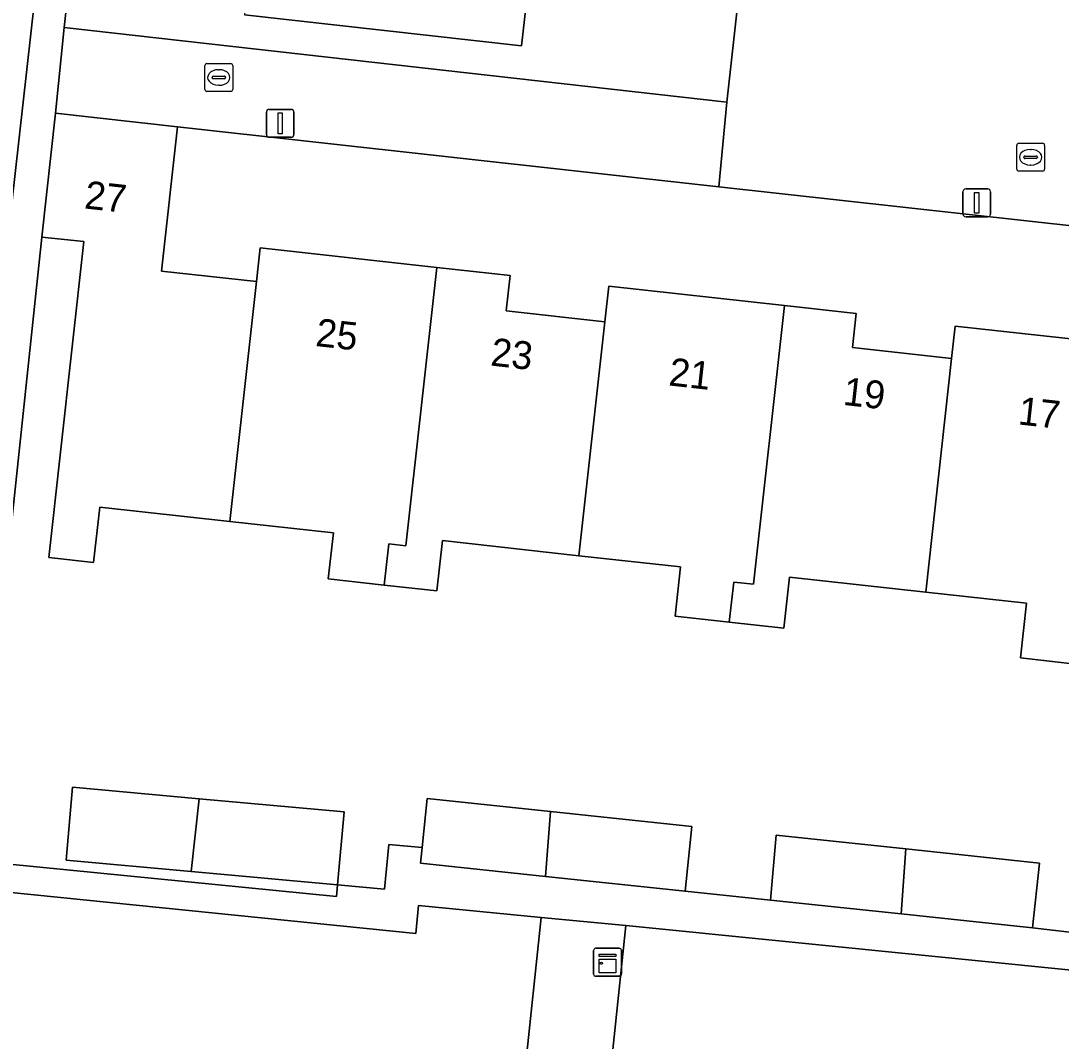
# Model space of a CAD drawing. Extents: x 162082 to 163401, y 388089 to 388636.
# Drawn here: x 162798.94 to 162836.27, y 388127.59 to 388164.2 of the extents above; entities that cross this region are included whole.
import ezdxf

# ---------------------------------------------------------------- set-up
doc = ezdxf.new("R2010")
doc.units = 0
for name, color, linetype in [('IMGEO_Brandkraan', 7, 'Continuous'), ('IMGEO_Erf', 7, 'Continuous'), ('IMGEO_Kast', 7, 'Continuous'), ('IMGEO_Lichtmast', 7, 'Continuous'), ('IMGEO_Muur', 7, 'Continuous'), ('IMGEO_Pand', 7, 'Continuous'), ('IMGEO_Pand_nummerreeks', 7, 'Continuous'), ('IMGEO_Rijbaan_lokaal_open', 7, 'Continuous'), ('IMGEO_Rioolput', 7, 'Continuous'), ('IMGEO_Voetpad_open', 7, 'Continuous')]:
    doc.layers.add(name, color=color, linetype=linetype)

msp = doc.modelspace()

# ---------------------------------------------------------------- linework, layer by layer
at = {"layer": 'IMGEO_Brandkraan'}
for p, q in [((162805.621, 388162.671), (162806.473, 388162.671)), ((162805.546, 388161.745), (162805.546, 388162.597)), ((162806.034, 388162.451), (162806.059, 388162.451)), ((162806.547, 388162.597), (162806.547, 388161.745)), ((162805.805, 388162.165), (162805.805, 388162.177)), ((162806.243, 388162.128), (162805.845, 388162.128)), ((162805.848, 388162.214), (162806.246, 388162.214)), ((162806.057, 388161.891), (162806.032, 388161.891)), ((162806.289, 388162.177), (162806.289, 388162.165)), ((162806.473, 388161.671), (162805.621, 388161.671))]:
    msp.add_line(p, q, dxfattribs=at)
for points in [[(162805.621, 388162.671), (162806.473, 388162.671)], [(162805.546, 388161.745), (162805.546, 388162.597)], [(162806.547, 388162.597), (162806.547, 388161.745)], [(162806.473, 388161.671), (162805.621, 388161.671)]]:
    msp.add_lwpolyline(points, dxfattribs=at)
for centre, radius, start, end in [((162805.623, 388162.595), 0.0765, 91.552, 178.448), ((162805.623, 388162.595), 0.0765, 91.552, 178.448), ((162806.471, 388162.595), 0.0765, 1.552, 88.448), ((162806.471, 388162.595), 0.0765, 1.552, 88.448), ((162805.845, 388162.174), 0.0403, 85.8775, 175.7526), ((162805.842, 388162.164), 0.0366, 178.938, 274.7102), ((162806.246, 388162.171), 0.043, 264.8664, 352.4533), ((162806.25, 388162.176), 0.0386, 1.7309, 96.639), ((162805.623, 388161.747), 0.0765, 181.552, 268.448), ((162805.623, 388161.747), 0.0765, 181.552, 268.448), ((162806.471, 388161.747), 0.0765, 271.552, 358.448), ((162806.471, 388161.747), 0.0765, 271.552, 358.448)]:
    msp.add_arc(centre, radius, start, end, dxfattribs=at)
for centre, major_axis, ratio, start_param, end_param in [((162806.033, 388162.171), (-0.387, 0.002), 0.722429, 4.712389, 7.853982), ((162806.058, 388162.171), (-0.39, 0.002), 0.717154, 1.570796, 4.712389)]:
    msp.add_ellipse(centre, major_axis=major_axis, ratio=ratio, start_param=start_param, end_param=end_param, dxfattribs=at)
at = {"layer": 'IMGEO_Erf'}
for points in [[(162795.979, 388134.212), (162803.844, 388204.258)], [(162804.95, 388204.136), (162800.498, 388163.968), (162808.249, 388163.092), (162824.27, 388161.282), (162825.928, 388176.279)], [(162817.345, 388167.21), (162816.908, 388163.305), (162806.971, 388164.418)], [(162836.884, 388141.113), (162834.808, 388141.342), (162835.025, 388143.308), (162831.408, 388143.708), (162826.524, 388144.247), (162826.321, 388142.407), (162824.357, 388142.624), (162822.419, 388142.838), (162822.614, 388144.609), (162818.966, 388145.012), (162814.072, 388145.552), (162813.873, 388143.749), (162811.98, 388143.958), (162809.974, 388144.179), (162810.156, 388145.829), (162806.447, 388146.239), (162801.775, 388146.755), (162801.556, 388144.773), (162799.953, 388144.95), (162801.204, 388156.281), (162799.702, 388156.447), (162797.324, 388134.069), (162810.27, 388132.785), (162810.308, 388133.203), (162811.995, 388133.05), (162812.141, 388134.654), (162813.336, 388134.54), (162813.522, 388136.303), (162817.949, 388135.835), (162823.02, 388135.3), (162822.774, 388132.978), (162825.835, 388132.655), (162826.044, 388134.981), (162830.698, 388134.49), (162835.484, 388133.985), (162835.239, 388131.662), (162842.925, 388130.761)], [(162854.896, 388128.313), (162820.645, 388131.737), (162819.814, 388123.748), (162825.983, 388123.05), (162832, 388122.369), (162832.125, 388123.472), (162834.954, 388123.15), (162834.829, 388122.049), (162838.019, 388121.688)]]:
    msp.add_lwpolyline(points, dxfattribs=at)
for points in [[(162851.871, 388155.185), (162845.948, 388155.819), (162823.979, 388158.253), (162804.563, 388160.404), (162803.991, 388155.225), (162807.402, 388154.848), (162807.536, 388156.057), (162813.862, 388155.358), (162816.5, 388155.067), (162816.36, 388153.795), (162819.896, 388153.404), (162820.037, 388154.684), (162826.336, 388153.989), (162828.913, 388153.704), (162828.779, 388152.483), (162832.337, 388152.09), (162832.466, 388153.25), (162838.801, 388152.55), (162841.344, 388152.269), (162841.201, 388150.977), (162844.809, 388150.578), (162844.952, 388151.873), (162851.481, 388151.152), (162851.565, 388152.023)], [(162817.616, 388132.026), (162813.209, 388132.465), (162813.117, 388131.452), (162774.618, 388135.355), (162754.126, 388137.65), (162753.09, 388128.162), (162759.25, 388127.458), (162765.261, 388126.772), (162771.273, 388126.085), (162777.284, 388125.399), (162783.297, 388124.712), (162789.309, 388124.025), (162795.321, 388123.339), (162801.333, 388122.652), (162807.344, 388121.965), (162813.503, 388121.262), (162816.444, 388120.926)], [(162810.308, 388133.203), (162805.054, 388133.679), (162800.565, 388134.086), (162800.802, 388136.703), (162805.344, 388136.292), (162810.545, 388135.82)]]:
    msp.add_lwpolyline(points, close=True, dxfattribs=at)
at = {"layer": 'IMGEO_Kast'}
for p, q in [((162819.566, 388130.924), (162820.407, 388130.924)), ((162820.407, 388130.924), (162819.566, 388130.924)), ((162819.491, 388129.999), (162819.491, 388130.84)), ((162819.491, 388130.84), (162819.491, 388129.999)), ((162820.491, 388130.849), (162820.491, 388130.008)), ((162820.491, 388130.008), (162820.491, 388130.849)), ((162820.416, 388129.924), (162819.575, 388129.924)), ((162819.575, 388129.924), (162820.416, 388129.924))]:
    msp.add_line(p, q, dxfattribs=at)
for points in [[(162819.686, 388130.714), (162820.286, 388130.714), (162820.286, 388130.629), (162819.686, 388130.629), (162819.686, 388130.714)], [(162819.686, 388130.539), (162820.286, 388130.539), (162820.286, 388130.05), (162819.686, 388130.05), (162819.686, 388130.539)]]:
    msp.add_lwpolyline(points, dxfattribs=at)
msp.add_circle((162819.77, 388130.388), 0.0377, dxfattribs=at)
for centre, start, end in [((162819.569, 388130.846), 92.4484, 184.2845), ((162819.569, 388130.846), 92.4484, 184.2845), ((162820.413, 388130.846), 2.4484, 94.2845), ((162820.413, 388130.846), 2.4484, 94.2845), ((162819.569, 388130.002), 182.4484, 274.2845), ((162819.569, 388130.002), 182.4484, 274.2845), ((162820.413, 388130.002), 272.4484, 4.2845), ((162820.413, 388130.002), 272.4484, 4.2845)]:
    msp.add_arc(centre, 0.0779, start, end, dxfattribs=at)
at = {"layer": 'IMGEO_Lichtmast'}
for p, q in [((162807.753, 388160.124), (162807.753, 388160.924)), ((162807.753, 388160.924), (162807.753, 388160.124)), ((162807.853, 388161.024), (162808.643, 388161.024)), ((162808.643, 388161.024), (162807.853, 388161.024)), ((162808.743, 388160.924), (162808.743, 388160.124)), ((162808.743, 388160.124), (162808.743, 388160.924)), ((162808.643, 388160.024), (162807.853, 388160.024)), ((162807.853, 388160.024), (162808.643, 388160.024)), ((162832.84, 388158.172), (162833.63, 388158.172)), ((162833.63, 388158.172), (162832.84, 388158.172)), ((162832.74, 388157.272), (162832.74, 388158.072)), ((162832.74, 388158.072), (162832.74, 388157.272)), ((162833.73, 388158.072), (162833.73, 388157.272)), ((162833.73, 388157.272), (162833.73, 388158.072)), ((162833.63, 388157.172), (162832.84, 388157.172)), ((162832.84, 388157.172), (162833.63, 388157.172))]:
    msp.add_line(p, q, dxfattribs=at)
for points in [[(162808.173, 388160.899), (162808.323, 388160.899), (162808.323, 388160.149), (162808.173, 388160.149), (162808.173, 388160.899)], [(162833.16, 388158.047), (162833.31, 388158.047), (162833.31, 388157.297), (162833.16, 388157.297), (162833.16, 388158.047)]]:
    msp.add_lwpolyline(points, dxfattribs=at)
for centre, start, end in [((162807.853, 388160.924), 90, 180), ((162807.853, 388160.924), 90, 180), ((162808.643, 388160.924), 0, 90), ((162808.643, 388160.924), 360, 90), ((162807.853, 388160.124), 180, 270), ((162807.853, 388160.124), 180, 270), ((162808.643, 388160.124), 270, 0), ((162808.643, 388160.124), 270, 0), ((162832.84, 388158.072), 90, 180), ((162832.84, 388158.072), 90, 180), ((162833.63, 388158.072), 0, 90), ((162833.63, 388158.072), 360, 90), ((162832.84, 388157.272), 180, 270), ((162832.84, 388157.272), 180, 270), ((162833.63, 388157.272), 270, 0), ((162833.63, 388157.272), 270, 0)]:
    msp.add_arc(centre, 0.1, start, end, dxfattribs=at)
at = {"layer": 'IMGEO_Muur'}
msp.add_lwpolyline([(162800.498, 388163.968), (162808.249, 388163.092)], dxfattribs=at)
at = {"layer": 'IMGEO_Pand'}
for points in [[(162809.728, 388174.626), (162809.314, 388170.93), (162807.72, 388171.109), (162807.527, 388169.387), (162806.971, 388164.418), (162816.908, 388163.305), (162817.345, 388167.21), (162818.835, 388167.043), (162819.561, 388173.523), (162818.4, 388173.653)], [(162807.402, 388154.848), (162803.991, 388155.225), (162804.563, 388160.404), (162800.192, 388160.886), (162799.702, 388156.447), (162801.204, 388156.281), (162799.953, 388144.95), (162801.556, 388144.773), (162801.775, 388146.755), (162806.447, 388146.239)], [(162807.402, 388154.848), (162806.447, 388146.239), (162810.156, 388145.829), (162809.974, 388144.179), (162811.98, 388143.958), (162812.144, 388145.437), (162812.758, 388145.369), (162813.862, 388155.358), (162807.536, 388156.057)], [(162819.896, 388153.404), (162816.36, 388153.795), (162816.5, 388155.067), (162813.862, 388155.358), (162812.758, 388145.369), (162812.144, 388145.437), (162811.98, 388143.958), (162813.873, 388143.749), (162814.072, 388145.552), (162818.966, 388145.012)], [(162819.896, 388153.404), (162818.966, 388145.012), (162822.614, 388144.609), (162822.419, 388142.838), (162824.357, 388142.624), (162824.517, 388144.067), (162825.23, 388143.988), (162826.336, 388153.989), (162820.037, 388154.684)], [(162824.357, 388142.624), (162826.321, 388142.407), (162826.524, 388144.247), (162831.408, 388143.708), (162832.337, 388152.09), (162828.779, 388152.483), (162828.913, 388153.704), (162826.336, 388153.989), (162825.23, 388143.988), (162824.517, 388144.067)], [(162838.801, 388152.55), (162832.466, 388153.25), (162832.337, 388152.09), (162831.408, 388143.708), (162835.025, 388143.308), (162834.808, 388141.342), (162836.884, 388141.113), (162837.059, 388142.688), (162837.703, 388142.616)], [(162805.344, 388136.292), (162800.802, 388136.703), (162800.565, 388134.086), (162805.054, 388133.679)], [(162805.344, 388136.292), (162805.054, 388133.679), (162810.308, 388133.203), (162810.545, 388135.82)], [(162817.949, 388135.835), (162813.522, 388136.303), (162813.336, 388134.54), (162813.277, 388133.981), (162817.772, 388133.506)], [(162817.949, 388135.835), (162817.772, 388133.506), (162822.774, 388132.978), (162823.02, 388135.3)], [(162830.698, 388134.49), (162826.044, 388134.981), (162825.835, 388132.655), (162830.521, 388132.16)], [(162830.698, 388134.49), (162830.521, 388132.16), (162835.239, 388131.662), (162835.484, 388133.985)]]:
    msp.add_lwpolyline(points, close=True, dxfattribs=at)
at = {"layer": 'IMGEO_Rijbaan_lokaal_open'}
msp.add_lwpolyline([(162847.12, 388166.739), (162848.03, 388175.302), (162848.456, 388179.167), (162849.399, 388187.886), (162849.808, 388191.587), (162850.603, 388199.107), (162828.788, 388201.496), (162828.347, 388197.774), (162827.717, 388192.459), (162827.301, 388188.741), (162826.346, 388180.019), (162825.928, 388176.279), (162824.27, 388161.282), (162823.979, 388158.253), (162845.948, 388155.819), (162846.154, 388157.848), (162846.709, 388163.018)], close=True, dxfattribs=at)
at = {"layer": 'IMGEO_Rioolput'}
for p, q in [((162834.671, 388158.884), (162834.671, 388159.736)), ((162834.746, 388159.81), (162835.598, 388159.81)), ((162835.672, 388159.736), (162835.672, 388158.884)), ((162834.93, 388159.304), (162834.93, 388159.316)), ((162834.973, 388159.353), (162835.371, 388159.353)), ((162835.159, 388159.59), (162835.184, 388159.59)), ((162835.414, 388159.316), (162835.414, 388159.304)), ((162835.368, 388159.267), (162834.97, 388159.267)), ((162835.182, 388159.03), (162835.157, 388159.03)), ((162835.598, 388158.81), (162834.746, 388158.81))]:
    msp.add_line(p, q, dxfattribs=at)
for points in [[(162834.671, 388158.884), (162834.671, 388159.736)], [(162834.746, 388159.81), (162835.598, 388159.81)], [(162835.672, 388159.736), (162835.672, 388158.884)], [(162835.598, 388158.81), (162834.746, 388158.81)]]:
    msp.add_lwpolyline(points, dxfattribs=at)
for centre, radius, start, end in [((162834.748, 388159.734), 0.0765, 91.552, 178.448), ((162834.748, 388159.734), 0.0765, 91.552, 178.448), ((162835.596, 388159.734), 0.0765, 1.552, 88.448), ((162835.596, 388159.734), 0.0765, 1.552, 88.448), ((162834.97, 388159.313), 0.0403, 85.8775, 175.7526), ((162834.967, 388159.303), 0.0366, 178.938, 274.7102), ((162835.371, 388159.31), 0.043, 264.8664, 352.4533), ((162835.375, 388159.315), 0.0386, 1.7309, 96.639), ((162834.748, 388158.886), 0.0765, 181.552, 268.448), ((162834.748, 388158.886), 0.0765, 181.552, 268.448), ((162835.596, 388158.886), 0.0765, 271.552, 358.448), ((162835.596, 388158.886), 0.0765, 271.552, 358.448)]:
    msp.add_arc(centre, radius, start, end, dxfattribs=at)
for centre, major_axis, ratio, start_param, end_param in [((162835.158, 388159.31), (-0.387, 0.002), 0.722429, 4.712389, 7.853982), ((162835.183, 388159.31), (-0.39, 0.002), 0.717154, 1.570796, 4.712389)]:
    msp.add_ellipse(centre, major_axis=major_axis, ratio=ratio, start_param=start_param, end_param=end_param, dxfattribs=at)
at = {"layer": 'IMGEO_Voetpad_open'}
for points in [[(162803.844, 388204.258), (162795.979, 388134.212)], [(162842.925, 388130.761), (162835.239, 388131.662), (162830.521, 388132.16), (162825.835, 388132.655), (162822.774, 388132.978), (162817.772, 388133.506), (162813.277, 388133.981), (162813.336, 388134.54), (162812.141, 388134.654), (162811.995, 388133.05), (162810.308, 388133.203), (162810.27, 388132.785), (162797.324, 388134.069), (162799.702, 388156.447), (162800.192, 388160.886), (162800.498, 388163.968), (162804.95, 388204.136)], [(162774.618, 388135.355), (162813.117, 388131.452), (162813.209, 388132.465), (162817.616, 388132.026), (162820.645, 388131.737), (162854.896, 388128.313)]]:
    msp.add_lwpolyline(points, dxfattribs=at)
for points in [[(162800.192, 388160.886), (162804.563, 388160.404), (162823.979, 388158.253), (162824.27, 388161.282), (162808.249, 388163.092), (162800.498, 388163.968)], [(162820.645, 388131.737), (162817.616, 388132.026), (162816.444, 388120.926), (162815.93, 388116.397), (162815.261, 388110.504), (162815.061, 388108.754), (162818.122, 388108.413), (162818.522, 388112.082), (162819.276, 388118.991), (162819.814, 388123.748)]]:
    msp.add_lwpolyline(points, close=True, dxfattribs=at)

# ---------------------------------------------------------------- texts
at = {"layer": 'IMGEO_Pand_nummerreeks'}
for s, rotation, p in [('27', 353.7073, (162801.197, 388157.475)), ('25', 353.6312, (162809.49, 388152.539)), ('23', 353.6312, (162815.768, 388151.838)), ('21', 353.6312, (162822.158, 388151.125)), ('19', 353.6312, (162828.414, 388150.426)), ('17', 353.6312, (162834.692, 388149.726))]:
    msp.add_text(s, height=1, rotation=rotation, dxfattribs=at).set_placement(p)

doc.saveas('drawing.dxf')
